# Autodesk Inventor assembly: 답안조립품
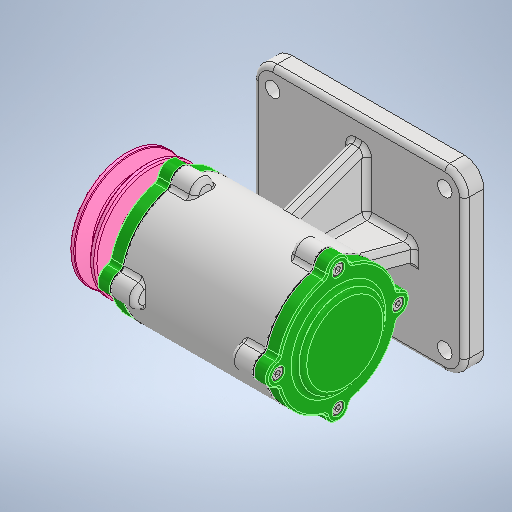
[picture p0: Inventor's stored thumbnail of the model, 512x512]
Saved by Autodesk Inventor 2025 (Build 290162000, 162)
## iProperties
Created: 2025-08
Part Number: 답안조립품
Document SubType Name: Assembly
Designer: infra02
Author: infra02
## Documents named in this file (12)
- C:\Users\infra02\Desktop\750806V1006\답안조립품.iam
- C:\Users\infra02\Desktop\750806V1006\본체.ipt
- C:\Users\infra02\Desktop\750806V1006\V-벨트풀리\V-벨트풀리.ipt
- C:\Users\infra02\Desktop\750806V1006\개스킷\개스킷.ipt
- C:\Users\infra02\Desktop\750806V1006\너트 M12 x 1.25\너트 M12 x 1.25.ipt
- C:\Users\infra02\Desktop\750806V1006\뒤커버\뒤커버.ipt
- C:\Users\infra02\Desktop\750806V1006\베어링 6204\베어링 6204.ipt
- C:\Users\infra02\Desktop\750806V1006\볼트 M4 x 12\볼트 M4 x 12.ipt
- C:\Users\infra02\Desktop\750806V1006\앞커버\앞커버.ipt
- C:\Users\infra02\Desktop\750806V1006\오일 실\오일 실.ipt
- C:\Users\infra02\Desktop\750806V1006\축\축.ipt
- C:\Users\infra02\Desktop\750806V1006\키 4 x 4\키 4 x 4.ipt
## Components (3 placed, 2 different names)
1. V-벨트풀리:1
2. 개스킷:1
3. 개스킷:2
